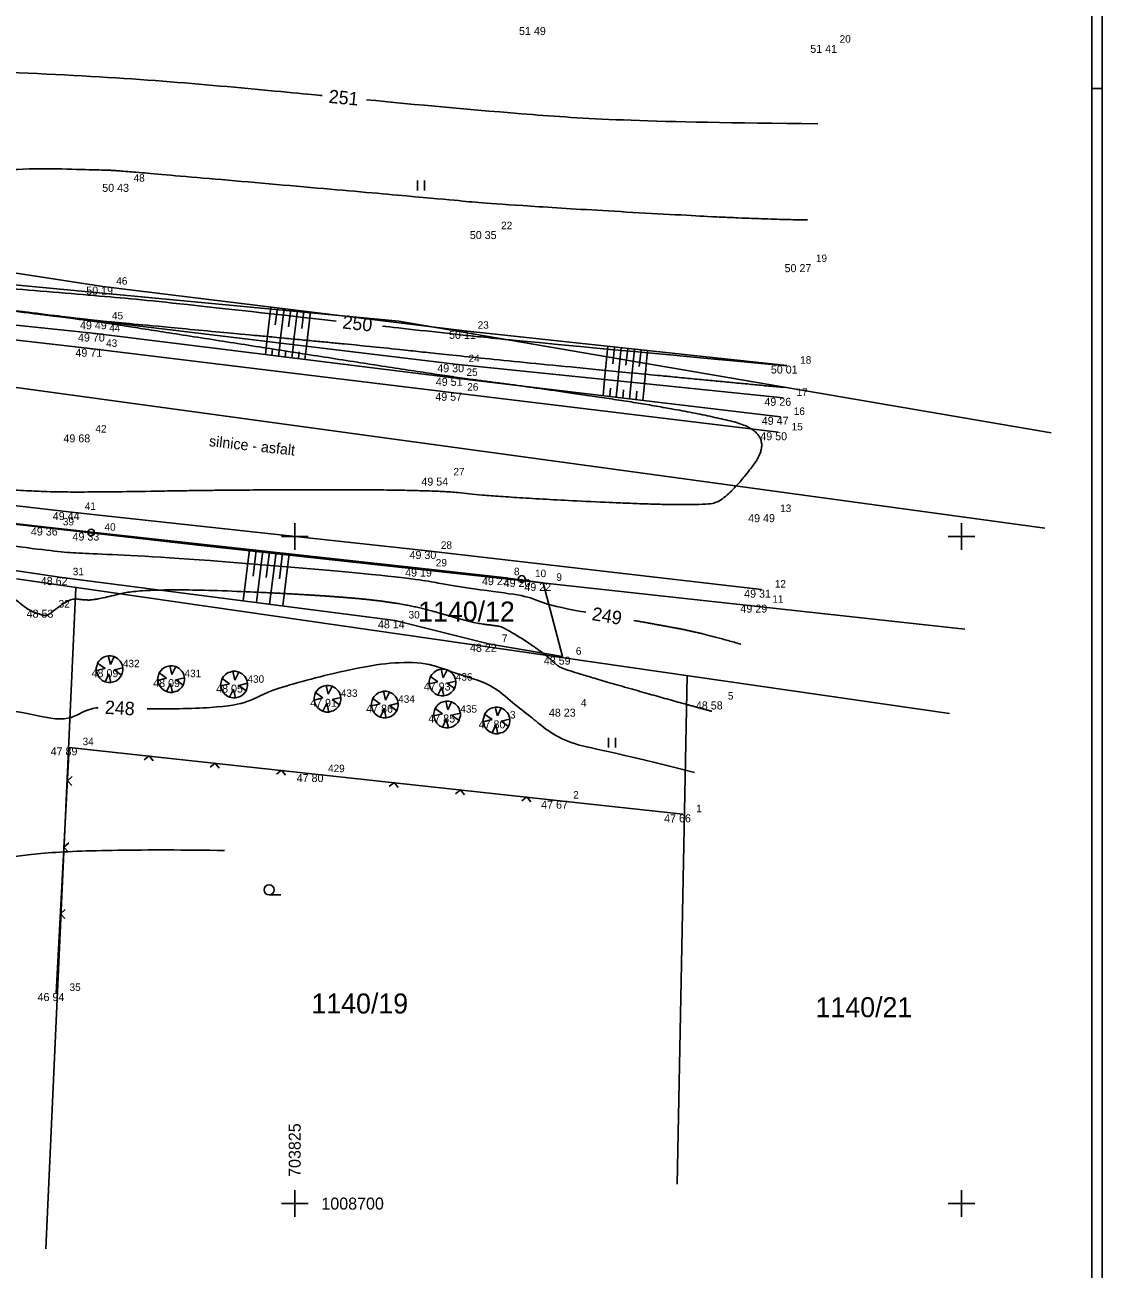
# Model space of a CAD drawing. Extents: x -704057 to -703795, y -1008732 to -1008584.
# Drawn here: x -703835.12 to -703794.73, y -1008702.46 to -1008655.82 of the extents above; entities that cross this region are included whole.
import ezdxf

# ---------------------------------------------------------------- set-up
doc = ezdxf.new("R2010")
doc.units = 0
for name, color, linetype in [('Z_body', 7, 'Continuous'), ('Z_body_cisla', 7, 'Continuous'), ('Z_body_vysky', 7, 'Continuous'), ('Z_hekt_sit', 7, 'Continuous'), ('Z_hekt_sit_popis', 7, 'Continuous'), ('Z_katastr_cisla_pozemkove', 7, 'Continuous'), ('Z_katastr_hranice', 7, 'Continuous'), ('Z_katastr_hranice_KU', 7, 'Continuous'), ('Z_komunikace_zpevn_pl', 7, 'Continuous'), ('Z_oploceni', 7, 'Continuous'), ('Z_plotbox', 7, 'Continuous'), ('Z_popis', 7, 'Continuous'), ('Z_ramecek_tisk', 7, 'Continuous'), ('Z_smer_sloupky', 7, 'Continuous'), ('Z_teren_hrany_paty', 7, 'Continuous'), ('Z_vrstevnice_popis', 7, 'Continuous'), ('Z_vrstevnice_vedlejsi', 7, 'Continuous'), ('Z_vstupy', 7, 'Continuous'), ('Z_zelen_jednotliva', 7, 'Continuous')]:
    doc.layers.add(name, color=color, linetype=linetype)

# ---------------------------------------------------------------- blocks, each defined once
blk = doc.blocks.new('POINT_DISPLAY')
blk.add_line((0, 0), (0, 0))
blk = doc.blocks.new('Z212')
for p, q in [((-0.17, 0.17), (0, 0)), ((0, 0), (0.17, 0.17))]:
    blk.add_line(p, q)
blk = doc.blocks.new('Z22')
for p, q in [((-0.23, 0.45), (-0.15, 0.47)), ((-0.15, 0.47), (-0.05, 0.5)), ((-0.05, 0.5), (0.05, 0.5)), ((-0.05, 0.5), (0.03, 0.17)), ((0.03, 0.17), (0.17, 0.47)), ((0.05, 0.5), (0.17, 0.47)), ((0.17, 0.47), (0.3, 0.4)), ((-0.5, 0.05), (-0.47, 0.15)), ((-0.5, -0.05), (-0.5, 0.05)), ((-0.5, -0.05), (-0.17, 0.03)), ((-0.47, 0.15), (-0.45, 0.23)), ((-0.45, 0.23), (-0.4, 0.3)), ((-0.17, 0.03), (-0.45, 0.23)), ((-0.4, 0.3), (-0.33, 0.38)), ((-0.33, 0.38), (-0.23, 0.45)), ((0.5, 0.05), (0.17, -0.03)), ((0.3, 0.4), (0.4, 0.3)), ((0.4, 0.3), (0.45, 0.23)), ((0.45, 0.23), (0.47, 0.15)), ((0.47, 0.15), (0.5, 0.05)), ((0.5, 0.05), (0.5, -0.05)), ((-0.47, -0.15), (-0.5, -0.05)), ((-0.45, -0.23), (-0.47, -0.15)), ((-0.38, -0.33), (-0.45, -0.23)), ((-0.28, -0.42), (-0.38, -0.33)), ((-0.17, -0.47), (-0.28, -0.42)), ((-0.17, -0.47), (-0.03, -0.17)), ((-0.03, -0.17), (0.05, -0.5)), ((0.23, -0.45), (0.15, -0.47)), ((0.17, -0.03), (0.45, -0.23)), ((0.33, -0.38), (0.23, -0.45)), ((0.4, -0.3), (0.33, -0.38)), ((0.45, -0.23), (0.4, -0.3)), ((0.47, -0.15), (0.45, -0.23)), ((0.5, -0.05), (0.47, -0.15)), ((-0.05, -0.5), (-0.17, -0.47)), ((0.05, -0.5), (-0.05, -0.5)), ((0.15, -0.47), (0.05, -0.5))]:
    blk.add_line(p, q)
blk = doc.blocks.new('Z306')
for p, q in [((-0.13, 0.17), (-0.13, -0.2)), ((0.13, 0.17), (0.13, -0.2))]:
    blk.add_line(p, q)
blk = doc.blocks.new('Z304')
blk.add_line((0, -0.19), (0.44, -0.19))
blk.add_circle((0, 0), 0.188)
blk = doc.blocks.new('Z15')
blk.add_circle((0, 0), 0.125)

msp = doc.modelspace()

# ---------------------------------------------------------------- linework, layer by layer
at = {"layer": 'Z_hekt_sit'}
for p, q in [((-703825, -1008674.5), (-703825, -1008675.5)), ((-703800, -1008674.5), (-703800, -1008675.5)), ((-703825.5, -1008675), (-703824.5, -1008675)), ((-703800.5, -1008675), (-703799.5, -1008675)), ((-703825, -1008699.5), (-703825, -1008700.5)), ((-703800, -1008699.5), (-703800, -1008700.5)), ((-703825.5, -1008700), (-703824.5, -1008700)), ((-703800.5, -1008700), (-703799.5, -1008700))]:
    msp.add_line(p, q, dxfattribs=at)
at = {"layer": 'Z_katastr_hranice'}
for p, q in [((-703892.72, -1008660.17), (-703821.1, -1008666.93)), ((-703821.1, -1008666.93), (-703796.64, -1008671.11)), ((-703871.83, -1008670.35), (-703828.51, -1008675.34)), ((-703828.51, -1008675.34), (-703799.88, -1008678.47)), ((-703800.45, -1008681.63), (-703835.43, -1008676.59)), ((-703834.33, -1008701.69), (-703833.21, -1008676.91)), ((-703810.29, -1008680.21), (-703810.66, -1008699.27))]:
    msp.add_line(p, q, dxfattribs=at)
at = {"layer": 'Z_katastr_hranice_KU'}
msp.add_line((-703853.02, -1008667), (-703796.88, -1008674.69), dxfattribs=at)
at = {"layer": 'Z_komunikace_zpevn_pl'}
for p, q in [((-703832.57, -1008667.96), (-703843.45, -1008666.74)), ((-703819.03, -1008669.61), (-703832.57, -1008667.96)), ((-703819.03, -1008669.61), (-703806.87, -1008671.09)), ((-703844.44, -1008672.81), (-703833.37, -1008674.08)), ((-703833.37, -1008674.08), (-703820.02, -1008675.54)), ((-703807.5, -1008676.99), (-703820.02, -1008675.54))]:
    msp.add_line(p, q, dxfattribs=at)
at = {"layer": 'Z_oploceni'}
for p, q in [((-703833.45, -1008682.9), (-703833.94, -1008692.11)), ((-703824.25, -1008683.9), (-703833.45, -1008682.9)), ((-703815.06, -1008684.9), (-703824.25, -1008683.9))]:
    msp.add_line(p, q, dxfattribs=at)
at = {"layer": 'Z_plotbox'}
for p, q in [((-703794.73, -1008583.96), (-703794.73, -1008732.46)), ((-703794.73, -1008658.21), (-703795.11, -1008658.21))]:
    msp.add_line(p, q, dxfattribs=at)
at = {"layer": 'Z_ramecek_tisk'}
msp.add_line((-703795.11, -1008584.34), (-703795.11, -1008732.09), dxfattribs=at)
at = {"layer": 'Z_teren_hrany_paty'}
for p, q in [((-703832.19, -1008665.63), (-703843.93, -1008663.81)), ((-703843.29, -1008665.58), (-703832.35, -1008666.93)), ((-703818.64, -1008667.29), (-703832.19, -1008665.63)), ((-703832.45, -1008667.39), (-703843.25, -1008666.28)), ((-703825.9, -1008666.4), (-703826.05, -1008667.69)), ((-703825.65, -1008666.43), (-703825.73, -1008667.07)), ((-703825.4, -1008666.46), (-703825.56, -1008667.75)), ((-703832.35, -1008666.93), (-703818.98, -1008668.54)), ((-703825.15, -1008666.49), (-703825.23, -1008667.14)), ((-703824.9, -1008666.52), (-703825.06, -1008667.81)), ((-703824.66, -1008666.55), (-703824.73, -1008667.2)), ((-703824.41, -1008666.58), (-703824.56, -1008667.87)), ((-703819.06, -1008669.05), (-703832.45, -1008667.39)), ((-703806.55, -1008668.59), (-703818.64, -1008667.29)), ((-703826.1, -1008668.18), (-703826.04, -1008667.69)), ((-703825.61, -1008668.24), (-703825.55, -1008667.75)), ((-703825.11, -1008668.3), (-703825.05, -1008667.81)), ((-703824.62, -1008668.36), (-703824.56, -1008667.87)), ((-703813.26, -1008667.87), (-703813.39, -1008669.11)), ((-703825.86, -1008668.21), (-703825.83, -1008667.96)), ((-703825.36, -1008668.27), (-703825.33, -1008668.02)), ((-703824.86, -1008668.33), (-703824.83, -1008668.08)), ((-703813.01, -1008667.9), (-703813.07, -1008668.52)), ((-703812.76, -1008667.92), (-703812.89, -1008669.16)), ((-703812.51, -1008667.95), (-703812.58, -1008668.57)), ((-703812.26, -1008667.98), (-703812.39, -1008669.22)), ((-703812.01, -1008668), (-703812.08, -1008668.62)), ((-703811.77, -1008668.03), (-703811.89, -1008669.27)), ((-703818.98, -1008668.54), (-703806.69, -1008669.8)), ((-703806.79, -1008670.51), (-703819.06, -1008669.05)), ((-703813.44, -1008669.72), (-703813.38, -1008669.11)), ((-703812.95, -1008669.78), (-703812.88, -1008669.17)), ((-703812.45, -1008669.84), (-703812.39, -1008669.22)), ((-703811.95, -1008669.9), (-703811.89, -1008669.27)), ((-703813.19, -1008669.75), (-703813.16, -1008669.44)), ((-703812.7, -1008669.81), (-703812.67, -1008669.5)), ((-703812.2, -1008669.87), (-703812.17, -1008669.55)), ((-703834.19, -1008674.66), (-703844.57, -1008673.51)), ((-703844.95, -1008674.86), (-703833.82, -1008676.52)), ((-703820.21, -1008676.2), (-703834.19, -1008674.66)), ((-703826.7, -1008675.49), (-703826.93, -1008677.41)), ((-703826.45, -1008675.51), (-703826.56, -1008676.48)), ((-703826.2, -1008675.54), (-703826.43, -1008677.47)), ((-703825.95, -1008675.57), (-703826.07, -1008676.54)), ((-703825.7, -1008675.59), (-703825.94, -1008677.53)), ((-703825.46, -1008675.62), (-703825.57, -1008676.59)), ((-703825.21, -1008675.65), (-703825.44, -1008677.6)), ((-703817.28, -1008676.52), (-703820.21, -1008676.2)), ((-703833.82, -1008676.52), (-703821.23, -1008678.14)), ((-703815.69, -1008676.74), (-703817.28, -1008676.52)), ((-703814.96, -1008679.5), (-703815.69, -1008676.74)), ((-703821.23, -1008678.14), (-703817.73, -1008679.02)), ((-703817.73, -1008679.02), (-703814.96, -1008679.5))]:
    msp.add_line(p, q, dxfattribs=at)
at = {"layer": 'Z_vrstevnice_popis'}
for points, degree in [([(-703900.886, -1008655.959), (-703899.024, -1008656.26), (-703894.071, -1008657.056), (-703890.313, -1008657.487), (-703881.983, -1008657.824), (-703876.324, -1008658.109), (-703871.084, -1008656.76), (-703869.237, -1008656.583), (-703868.601, -1008656.623), (-703856.36, -1008656.952), (-703852.392, -1008657.193), (-703842.819, -1008657.404), (-703836.655, -1008657.542), (-703831.19, -1008657.812), (-703826.999, -1008658.179), (-703824.254, -1008658.442), (-703823.966, -1008658.47)], 3), ([(-703822.307, -1008658.63), (-703820.55, -1008658.799), (-703815.93, -1008659.235), (-703811.932, -1008659.471), (-703805.39, -1008659.526)], 3), ([(-703866.94, -1008667.434), (-703866.032, -1008667.372), (-703863.34, -1008667.075), (-703861.725, -1008665.569), (-703860.311, -1008664.545), (-703863.717, -1008663.91), (-703866.193, -1008663.489), (-703868.465, -1008663.178), (-703870.115, -1008662.896), (-703877.36, -1008661.542), (-703870.689, -1008662.276), (-703869.999, -1008662.227), (-703861.026, -1008662.976), (-703856.707, -1008663.374), (-703852.831, -1008663.809), (-703845.902, -1008664.503), (-703843.668, -1008664.535), (-703838.357, -1008665.417), (-703836.381, -1008665.655), (-703832.233, -1008665.983), (-703829.782, -1008666.213), (-703825.08, -1008666.738), (-703823.448, -1008666.921)], 3), ([(-703821.709, -1008667.115), (-703821.113, -1008667.181), (-703818.068, -1008667.52), (-703817.094, -1008667.615), (-703806.552, -1008668.606)], 3), ([(-703875.185, -1008672.765), (-703874.223, -1008672.756), (-703870.137, -1008672.712), (-703865.404, -1008672.596), (-703857.13, -1008673.191), (-703849.187, -1008673.851), (-703844.786, -1008674.276), (-703839.886, -1008674.766), (-703834.01, -1008675.565), (-703833.183, -1008675.626), (-703829.469, -1008675.762), (-703820.395, -1008676.551), (-703819.724, -1008676.752), (-703817.382, -1008677.089), (-703816.139, -1008677.242), (-703815.655, -1008677.56), (-703814.182, -1008677.821), (-703814.089, -1008677.838)], 3), ([(-703812.282, -1008678.145), (-703811.09, -1008678.355), (-703809.677, -1008678.633), (-703808.272, -1008679.033)], 2), ([(-703830.53, -1008681.461), (-703829.811, -1008681.469), (-703827.88, -1008681.431), (-703826.666, -1008681.22), (-703826.02, -1008680.739), (-703822.776, -1008679.93), (-703821.425, -1008679.72), (-703820.05, -1008679.693), (-703819.042, -1008680.12), (-703817.573, -1008680.523), (-703816.805, -1008681.285), (-703816.193, -1008681.685), (-703814.889, -1008682.867), (-703813.027, -1008683.048), (-703810.01, -1008683.847)], 3), ([(-703853.857, -1008682.453), (-703845.141, -1008682.991), (-703842.815, -1008682.602), (-703837.88, -1008681.328), (-703835.453, -1008681.475), (-703833.605, -1008682.013), (-703832.889, -1008681.487), (-703832.436, -1008681.417), (-703832.363, -1008681.41)], 3)]:
    msp.add_open_spline(points, degree=degree, dxfattribs=at)
at = {"layer": 'Z_vrstevnice_vedlejsi'}
for points in [[(-703944.218, -1008669.537), (-703942.215, -1008669.847), (-703941.835, -1008669.79), (-703940.983, -1008669.911), (-703940.538, -1008669.059), (-703940.441, -1008669.011), (-703939.659, -1008668.87), (-703938.392, -1008666.573), (-703937.218, -1008665.198), (-703936.994, -1008664.158), (-703936.811, -1008663.182), (-703935.504, -1008662.788), (-703930.851, -1008662.989), (-703930.683, -1008662.945), (-703930.514, -1008662.948), (-703928.53, -1008663.14), (-703926.451, -1008662.869), (-703924.285, -1008662.962), (-703918.453, -1008660.188), (-703917.529, -1008662.583), (-703908.804, -1008661.73), (-703914.417, -1008658.58), (-703914.255, -1008657.775), (-703916.458, -1008657.408), (-703916.075, -1008656.975), (-703916.505, -1008656.883), (-703916.435, -1008655.703), (-703915.746, -1008656.007), (-703915.438, -1008656.225), (-703913.541, -1008656.36), (-703913.202, -1008656.502), (-703907.93, -1008657.256), (-703905.824, -1008657.417), (-703900.033, -1008658.024), (-703894.345, -1008658.848), (-703890.179, -1008659.57), (-703887.702, -1008659.871), (-703882.266, -1008660.175), (-703878.347, -1008660.959), (-703873.149, -1008661.531), (-703869.803, -1008661.293), (-703867.148, -1008661.514), (-703856.66, -1008662.48), (-703848.555, -1008661.935), (-703843.582, -1008661.747), (-703840.018, -1008661.713), (-703835.656, -1008661.182), (-703832.168, -1008661.259), (-703831.497, -1008661.293), (-703819.488, -1008662.346), (-703817.521, -1008662.543), (-703807.841, -1008663.114), (-703805.78, -1008663.132)], [(-703806.645, -1008669.413), (-703810.064, -1008669.091), (-703818.896, -1008668.231), (-703821.949, -1008667.886), (-703832.348, -1008666.911), (-703832.429, -1008666.905), (-703837.82, -1008666.255), (-703832.713, -1008666.908), (-703832.355, -1008666.952), (-703825.705, -1008667.99), (-703819.056, -1008669.026), (-703815.993, -1008669.415), (-703810.462, -1008670.24), (-703806.87, -1008671.09), (-703808.766, -1008673.591), (-703809.75, -1008673.886), (-703817.454, -1008673.52), (-703819.628, -1008673.248), (-703826.836, -1008673.24), (-703833.27, -1008673.353), (-703835.286, -1008673.278), (-703844.44, -1008672.81), (-703850.152, -1008672.821), (-703855.806, -1008672.275), (-703857.13, -1008672.165), (-703860.162, -1008671.947), (-703871.237, -1008671.005), (-703876.973, -1008670.473), (-703883.276, -1008669.953), (-703888.652, -1008669.207), (-703892.007, -1008668.787), (-703895.701, -1008668.459), (-703900.931, -1008667.965), (-703907.22, -1008668.487), (-703913.351, -1008668.979), (-703918.495, -1008669.549), (-703927.701, -1008668.863), (-703930.6, -1008669.724), (-703932.124, -1008670.909), (-703936.972, -1008673.376)], [(-703896.98, -1008678.651), (-703896.133, -1008678.493), (-703895.427, -1008678.464), (-703883.839, -1008678.545), (-703877.35, -1008677.837), (-703872.416, -1008677.342), (-703866.301, -1008677.05), (-703856.707, -1008676.518), (-703852.893, -1008676.277), (-703845.162, -1008676.191), (-703841.604, -1008676.353), (-703835.881, -1008677.017), (-703835.026, -1008677.731), (-703834.61, -1008677.894), (-703834.308, -1008677.982), (-703834.186, -1008677.892), (-703833.394, -1008677.301), (-703832.871, -1008677.385), (-703832.441, -1008677.368), (-703830.672, -1008676.925), (-703824.679, -1008677.145), (-703820.88, -1008677.475), (-703818.446, -1008678.206), (-703817.605, -1008678.327), (-703817.159, -1008678.382), (-703815.634, -1008679.383), (-703815.241, -1008679.772), (-703814.913, -1008679.988), (-703810.519, -1008681.242), (-703809.363, -1008681.548)], [(-703839.334, -1008687.561), (-703838.109, -1008687.245), (-703837.269, -1008687.296), (-703833.651, -1008686.681), (-703827.63, -1008686.764)]]:
    msp.add_open_spline(points, degree=2, dxfattribs=at)
at = {"layer": 'Z_vstupy'}
msp.add_line((-703810.45, -1008685.41), (-703815.06, -1008684.9), dxfattribs=at)

# ---------------------------------------------------------------- block references
at = {"layer": 'Z_body'}
for p in [(-703815.94, -1008655.9), (-703805.07, -1008656.57), (-703831.54, -1008661.78), (-703817.76, -1008663.55), (-703805.96, -1008664.79), (-703832.19, -1008665.63), (-703832.35, -1008666.93), (-703832.45, -1008667.39), (-703818.64, -1008667.29), (-703832.57, -1008667.96), (-703818.98, -1008668.54), (-703806.55, -1008668.59), (-703819.06, -1008669.05), (-703819.03, -1008669.61), (-703806.69, -1008669.8), (-703806.79, -1008670.51), (-703806.87, -1008671.09), (-703832.97, -1008671.17), (-703819.55, -1008672.79), (-703833.37, -1008674.08), (-703807.3, -1008674.16), (-703834.19, -1008674.66), (-703832.63, -1008674.85), (-703820.02, -1008675.54), (-703820.21, -1008676.2), (-703833.82, -1008676.52), (-703817.28, -1008676.52), (-703816.49, -1008676.59), (-703815.69, -1008676.74), (-703807.5, -1008676.99), (-703807.59, -1008677.55), (-703834.35, -1008677.74), (-703821.23, -1008678.14), (-703817.73, -1008679.02), (-703814.96, -1008679.5), (-703831.94, -1008679.97), (-703829.63, -1008680.34), (-703819.46, -1008680.47), (-703827.27, -1008680.55), (-703823.77, -1008681.08), (-703821.62, -1008681.3), (-703809.26, -1008681.18), (-703819.29, -1008681.67), (-703814.77, -1008681.45), (-703817.43, -1008681.89), (-703833.45, -1008682.9), (-703824.25, -1008683.9), (-703815.06, -1008684.9), (-703810.45, -1008685.41), (-703833.94, -1008692.11)]:
    msp.add_blockref('POINT_DISPLAY', p, dxfattribs=at)
at = {"layer": 'Z_oploceni'}
for p, rotation in [((-703830.46, -1008683.22), 173.8), ((-703827.98, -1008683.49), 173.8), ((-703825.49, -1008683.76), 173.8), ((-703833.52, -1008684.15), -93.00000000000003), ((-703821.27, -1008684.22), 173.8), ((-703818.79, -1008684.49), 173.8), ((-703816.3, -1008684.76), 173.8), ((-703833.65, -1008686.64), -93.00000000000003), ((-703833.78, -1008689.14), -93.00000000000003)]:
    msp.add_blockref('Z212', p, dxfattribs=dict(at, rotation=rotation))
at = {"layer": 'Z_popis'}
for name, p in [('Z306', (-703820.26, -1008661.83)), ('Z306', (-703813.1, -1008682.71)), ('Z304', (-703825.96, -1008688.24))]:
    msp.add_blockref(name, p, dxfattribs=at)
at = {"layer": 'Z_smer_sloupky'}
for p in [(-703832.63, -1008674.85), (-703816.49, -1008676.59)]:
    msp.add_blockref('Z15', p, dxfattribs=at)
at = {"layer": 'Z_zelen_jednotliva'}
for p in [(-703831.94, -1008679.97), (-703829.63, -1008680.34), (-703819.46, -1008680.47), (-703827.27, -1008680.55), (-703823.77, -1008681.08), (-703821.62, -1008681.3), (-703819.29, -1008681.67), (-703817.43, -1008681.89)]:
    msp.add_blockref('Z22', p, dxfattribs=at)

# ---------------------------------------------------------------- texts
at = {"layer": 'Z_body_cisla'}
for s, p in [('20', (-703804.57, -1008656.49)), ('48', (-703831.04, -1008661.7)), ('22', (-703817.26, -1008663.48)), ('19', (-703805.46, -1008664.71)), ('46', (-703831.69, -1008665.56)), ('45', (-703831.85, -1008666.86)), ('23', (-703818.14, -1008667.21)), ('44', (-703831.95, -1008667.32)), ('43', (-703832.07, -1008667.89)), ('24', (-703818.48, -1008668.46)), ('18', (-703806.05, -1008668.52)), ('25', (-703818.56, -1008668.98)), ('26', (-703818.53, -1008669.53)), ('17', (-703806.19, -1008669.73)), ('16', (-703806.29, -1008670.44)), ('42', (-703832.47, -1008671.1)), ('15', (-703806.37, -1008671.02)), ('27', (-703819.05, -1008672.71)), ('41', (-703832.87, -1008674)), ('13', (-703806.8, -1008674.08)), ('39', (-703833.69, -1008674.58)), ('40', (-703832.13, -1008674.78)), ('28', (-703819.52, -1008675.46)), ('31', (-703833.32, -1008676.45)), ('29', (-703819.71, -1008676.12)), ('8', (-703816.78, -1008676.45)), ('10', (-703815.99, -1008676.52)), ('9', (-703815.19, -1008676.66)), ('12', (-703807, -1008676.91)), ('11', (-703807.09, -1008677.48)), ('32', (-703833.85, -1008677.66)), ('30', (-703820.73, -1008678.07)), ('7', (-703817.23, -1008678.95)), ('6', (-703814.46, -1008679.43)), ('432', (-703831.44, -1008679.9)), ('431', (-703829.13, -1008680.27)), ('430', (-703826.77, -1008680.48)), ('436', (-703818.96, -1008680.4)), ('433', (-703823.27, -1008681.01)), ('5', (-703808.76, -1008681.11)), ('434', (-703821.12, -1008681.23)), ('435', (-703818.79, -1008681.6)), ('4', (-703814.27, -1008681.37)), ('3', (-703816.93, -1008681.82)), ('34', (-703832.95, -1008682.82)), ('429', (-703823.75, -1008683.83)), ('2', (-703814.56, -1008684.82)), ('1', (-703809.95, -1008685.33)), ('35', (-703833.44, -1008692.03))]:
    msp.add_text(s, height=0.28, dxfattribs=at).set_placement(p)
at = {"layer": 'Z_body_vysky'}
for s, p in [('51 49', (-703816.59, -1008656.2)), ('51 41', (-703805.67, -1008656.87)), ('50 43', (-703832.215, -1008662.08)), ('50 35', (-703818.435, -1008663.85)), ('50 27', (-703806.635, -1008665.09)), ('50 19', (-703832.815, -1008665.93)), ('49 49', (-703833.05, -1008667.23)), ('49 70', (-703833.125, -1008667.69)), ('50 11', (-703819.215, -1008667.59)), ('49 71', (-703833.22, -1008668.26)), ('49 30', (-703819.655, -1008668.84)), ('50 01', (-703807.15, -1008668.89)), ('49 51', (-703819.71, -1008669.35)), ('49 57', (-703819.73, -1008669.91)), ('49 26', (-703807.39, -1008670.1)), ('49 47', (-703807.49, -1008670.81)), ('49 50', (-703807.545, -1008671.39)), ('49 68', (-703833.67, -1008671.47)), ('49 54', (-703820.25, -1008673.09)), ('49 44', (-703834.07, -1008674.38)), ('49 49', (-703808, -1008674.46)), ('49 36', (-703834.89, -1008674.96)), ('49 33', (-703833.33, -1008675.15)), ('49 30', (-703820.695, -1008675.84)), ('49 19', (-703820.86, -1008676.5)), ('48 62', (-703834.52, -1008676.82)), ('49 23', (-703817.98, -1008676.82)), ('49 20', (-703817.165, -1008676.89)), ('49 22', (-703816.39, -1008677.04)), ('49 31', (-703808.15, -1008677.29)), ('49 29', (-703808.29, -1008677.85)), ('48 53', (-703835.05, -1008678.04)), ('48 14', (-703821.88, -1008678.44)), ('48 22', (-703818.43, -1008679.32)), ('48 59', (-703815.66, -1008679.8)), ('48 09', (-703832.615, -1008680.27)), ('48 09', (-703830.305, -1008680.64)), ('47 93', (-703820.16, -1008680.77)), ('48 05', (-703827.945, -1008680.85)), ('47 91', (-703824.42, -1008681.38)), ('47 86', (-703822.32, -1008681.6)), ('48 58', (-703809.96, -1008681.48)), ('47 85', (-703819.99, -1008681.97)), ('48 23', (-703815.47, -1008681.75)), ('47 80', (-703818.105, -1008682.19)), ('47 89', (-703834.15, -1008683.2)), ('47 80', (-703824.925, -1008684.2)), ('47 67', (-703815.76, -1008685.2)), ('47 66', (-703811.15, -1008685.71)), ('46 94', (-703834.64, -1008692.41))]:
    msp.add_text(s, height=0.3, dxfattribs=at).set_placement(p)
at = {"layer": 'Z_hekt_sit_popis'}
msp.add_text('703825', height=0.45, rotation=90, dxfattribs=at).set_placement((-703824.775, -1008699))
msp.add_text('1008700', height=0.45, dxfattribs=at).set_placement((-703824, -1008700.225))
at = {"layer": 'Z_katastr_cisla_pozemkove'}
for s, p in [('1140/12', (-703820.373, -1008678.185)), ('1140/19', (-703824.373, -1008692.875)), ('1140/21', (-703805.473, -1008693.015))]:
    msp.add_text(s, height=0.75, dxfattribs=at).set_placement(p)
at = {"layer": 'Z_popis'}
msp.add_text('silnice - asfalt', height=0.4, rotation=353.7, dxfattribs=at).set_placement((-703828.23, -1008671.61))
at = {"layer": 'Z_vrstevnice_popis'}
for s, rotation, p in [('251', 354.4915, (-703823.741, -1008658.743)), ('250', 353.6236, (-703823.228, -1008667.197)), ('249', 350.4643, (-703813.884, -1008678.127)), ('248', 356.876, (-703832.126, -1008681.643))]:
    msp.add_text(s, height=0.5, rotation=rotation, dxfattribs=at).set_placement(p)

doc.saveas('drawing.dxf')
